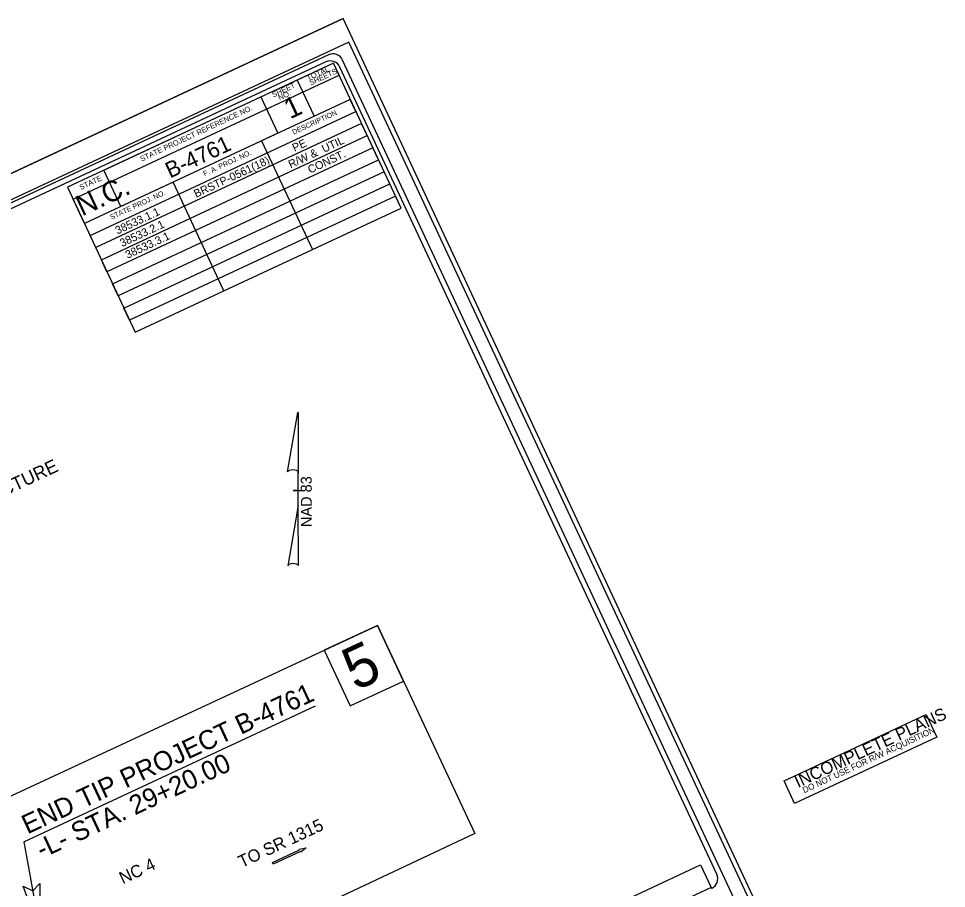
# Model space of a CAD drawing. Extents: x 2318983 to 2324558, y 920396 to 924651.
# Drawn here: x 2322471 to 2324558, y 922694 to 924651 of the extents above; entities that cross this region are included whole.
import ezdxf

# ---------------------------------------------------------------- set-up
doc = ezdxf.new("R2010")
doc.units = 0
for name, color, linetype in [('Prop Dimension', 7, 'Continuous'), ('Prop DSN Text', 7, 'Continuous'), ('Prop North Arrow NAD83 for Plan Sheets CELL', 7, 'Continuous'), ('Prop Terminator CELL', 7, 'Continuous'), ('Sheet Cutting Line CELL', 7, 'Continuous'), ('Sheet Data Field CELL', 7, 'Continuous'), ('Sheet Plot Border Inside CELL', 7, 'Continuous'), ('Sheet Plot Border Outside CELL', 7, 'Continuous'), ('Sheet Sticker Exception Certification CELL', 7, 'Continuous'), ('Sheet Sticker Incomplete CELL', 7, 'Continuous'), ('Sheet Title CELL', 7, 'Continuous')]:
    doc.layers.add(name, color=color, linetype=linetype)

msp = doc.modelspace()

# ---------------------------------------------------------------- linework, layer by layer
at = {"layer": 'Prop Dimension'}
for p, q in [((2322100.4, 922737.9), (2323278.1, 923286)), ((2323278.1, 923286), (2323496.8, 922818)), ((2323496.8, 922818), (2322321.6, 922264.7))]:
    msp.add_line(p, q, dxfattribs=at)
msp.add_lwpolyline([(2323278.1, 923286), (2323158, 923229.9), (2323216.5, 923104.6), (2323336.6, 923160.6)], close=True, dxfattribs=at)
at = {"layer": 'Prop DSN Text'}
for p, q in [((2322482.6, 922798.7), (2323138.3, 923104.7)), ((2322482.6, 922798.7), (2322519.1, 922595.5)), ((2323041.8, 922752.5), (2323102.7, 922780.9)), ((2323101.9, 922782.5), (2323117.2, 922785.6)), ((2323102.7, 922780.9), (2323101.9, 922782.5)), ((2323117.2, 922785.6), (2323105.1, 922775.7)), ((2323104.4, 922777.3), (2323043.5, 922748.9)), ((2323105.1, 922775.7), (2323104.4, 922777.3)), ((2323043.5, 922748.9), (2323041.8, 922752.5))]:
    msp.add_line(p, q, dxfattribs=at)
at = {"layer": 'Prop North Arrow NAD83 for Plan Sheets CELL'}
for p, q in [((2323075.7, 923631.5), (2323099, 923765.1)), ((2323099.1, 923765.1), (2323099, 923765.1)), ((2323099.1, 923765.1), (2323099, 923765.1)), ((2323099.1, 923765.1), (2323099.5, 923627.4)), ((2323099.7, 923556), (2323099.5, 923631.4)), ((2323099.5, 923627.4), (2323099.5, 923631.3)), ((2323088.1, 923589.4), (2323087.9, 923589.4)), ((2323098.3, 923589.4), (2323088.1, 923589.4)), ((2323088.2, 923589.4), (2323111.2, 923589.4)), ((2323099.7, 923556), (2323076, 923419.8)), ((2323100.2, 923420.5), (2323099.7, 923556))]:
    msp.add_line(p, q, dxfattribs=at)
for centre, start_param, end_param in [((2323087.6, 923630.1), 0.216388, 2.908219), ((2323088.2, 923419.4), 0.201328, 3.141593)]:
    msp.add_ellipse(centre, major_axis=(12.2, -0.1), ratio=0.461098, start_param=start_param, end_param=end_param, dxfattribs=at)
at = {"layer": 'Prop Terminator CELL'}
msp.add_lwpolyline([(2322518.3, 922705.1), (2322519.1, 922595.5), (2322481, 922699), (2322502.3, 922688.8)], close=True, dxfattribs=at)
at = {"layer": 'Sheet Cutting Line CELL'}
msp.add_line((2319538.3, 922942), (2323200.7, 924651.2), dxfattribs=at)
at = {"layer": 'Sheet Plot Border Inside CELL'}
msp.add_lwpolyline([(2320660.3, 920611.7), (2324284.6, 922303.2), (2323213.7, 924597.8), (2319589.4, 922906.3)], close=True, dxfattribs=at)
at = {"layer": 'Sheet Plot Border Outside CELL'}
msp.add_lwpolyline([(2323200.7, 924651.2), (2319538.3, 922942), (2320654.8, 920549.7), (2324317.2, 922258.9)], close=True, dxfattribs=at)
at = {"layer": 'Sheet Sticker Exception Certification CELL'}
for p, q in [((2323569.4, 922544.3), (2324004.5, 922747.3)), ((2324004.5, 922747.3), (2324028.3, 922696.2)), ((2324028.3, 922696.2), (2323593.3, 922493.2))]:
    msp.add_line(p, q, dxfattribs=at)
at = {"layer": 'Sheet Sticker Incomplete CELL'}
msp.add_lwpolyline([(2324216.1, 922885.4), (2324192.3, 922936.5), (2324512, 923085.7), (2324535.8, 923034.6)], close=True, dxfattribs=at)
at = {"layer": 'Sheet Title CELL'}
for points in [[(2323167.4, 924569.4), (2319948.6, 923067.3)], [(2323161.6, 924553.5), (2320073.4, 923112.2)], [(2324244.7, 922317.8), (2323199.2, 924557.8)], [(2322732.8, 923945.6), (2323330.9, 924224.7), (2323318.2, 924251.8), (2322720.1, 923972.7), (2322707.5, 923999.9), (2323305.5, 924279), (2323292.8, 924306.2), (2322694.8, 924027.1), (2322682.1, 924054.3), (2323280.1, 924333.4), (2323267.5, 924360.6), (2322669.4, 924081.5), (2322656.7, 924108.6), (2323254.8, 924387.8), (2323242.1, 924414.9), (2322644, 924135.8), (2322631.3, 924163), (2323229.4, 924442.1), (2323216.7, 924469.3), (2322618.6, 924190.2), (2322593.3, 924244.6), (2323191.3, 924523.7), (2323178.6, 924550.9), (2322580.6, 924271.7), (2322732.8, 923945.6), (2322932.2, 924038.6), (2322818, 924283.2), (2322700.2, 924228.3), (2322662.1, 924309.8), (2323015.6, 924474.8), (2323053.6, 924393.2), (2323017.3, 924376.3), (2323131.5, 924131.6), (2323330.9, 924224.7), (2323178.6, 924550.9), (2323097.1, 924512.8), (2323135.2, 924431.3)], [(2324041, 922725.9), (2323193.4, 924541.9)]]:
    msp.add_lwpolyline(points, dxfattribs=at)
for centre, start, end in [((2323171.7, 924531.9), 25.0187, 115.0187), ((2323177.5, 924547.8), 25.0187, 115.0187), ((2324019.2, 922715.9), 295.0187, 25.0187)]:
    msp.add_arc(centre, 24, start, end, dxfattribs=at)

# ---------------------------------------------------------------- texts
at = {"layer": 'Prop DSN Text'}
for s, height, rotation, p in [('5', 96, 24.9913, (2323228.3, 923137.6)), ('END TIP PROJECT B-4761', 43.2, 25.0187, (2322490.5, 922815.5)), ('-L- STA. 29+20.00', 43.2, 25.0187, (2322522.7, 922760.6)), ('TO SR 1315', 27.68, 25.0187, (2322972.6, 922740)), ('NC 4', 27.68, 25.0187, (2322704.9, 922703.2))]:
    msp.add_text(s, height=height, rotation=rotation, dxfattribs=at).set_placement(p)
at = {"layer": 'Prop North Arrow NAD83 for Plan Sheets CELL'}
msp.add_text('NAD 83', height=24.48, rotation=90.1503, dxfattribs=at).set_placement((2323130.1, 923507))
at = {"layer": 'Sheet Data Field CELL'}
for s, height, p in [('B-4761', 36, (2322811.2, 924291.2)), ('R/W &  UTIL', 18, (2323082.5, 924313.9)), ('  PE      ', 18, (2323079.1, 924345.6)), ('CONST.', 18, (2323126.3, 924302.1)), ('BRSTP-0561(18)', 18, (2322869.9, 924247.7)), ('38533.1.1 ', 18, (2322693.1, 924165.2)), ('38533.2.1 ', 18, (2322703.4, 924136.9)), ('38533.3.1 ', 18, (2322715.7, 924110.5)), ('GRADING, DRAINAGE, PAVING AND STRUCTURE ', 30, (2321704, 923233.3))]:
    msp.add_text(s, height=height, rotation=25.0187, dxfattribs=at).set_placement(p)
at = {"layer": 'Sheet Sticker Incomplete CELL'}
for s, height, p in [('INCOMPLETE PLANS', 27.648, (2324223.7, 922919.9)), ('DO NOT USE FOR R/W ACQUISITION', 13.824, (2324237.8, 922908.1))]:
    msp.add_text(s, height=height, rotation=25.0187, dxfattribs=at).set_placement(p)
at = {"layer": 'Sheet Title CELL'}
for s, height, p in [('TOTAL', 12, (2323122.2, 924510.9)), ('SHEETS', 12, (2323128, 924500.4)), ('SHEET', 12, (2323043.9, 924473.4)), ('NO.', 12, (2323057.9, 924466.9)), ('1', 46.4, (2323081.1, 924424.2)), ('STATE PROJECT REFERENCE NO.', 12, (2322747.4, 924329.1)), ('DESCRIPTION', 11.52, (2323089.3, 924389.6)), ('F. A. PROJ. NO.', 11.52, (2322889, 924296.1)), ('N.C.', 46.44, (2322613.3, 924205.9)), ('STATE', 12, (2322610.7, 924265.3)), ('STATE PROJ. NO.', 11.52, (2322679.6, 924198.4))]:
    msp.add_text(s, height=height, rotation=25.0187, dxfattribs=at).set_placement(p)

doc.saveas('drawing.dxf')
